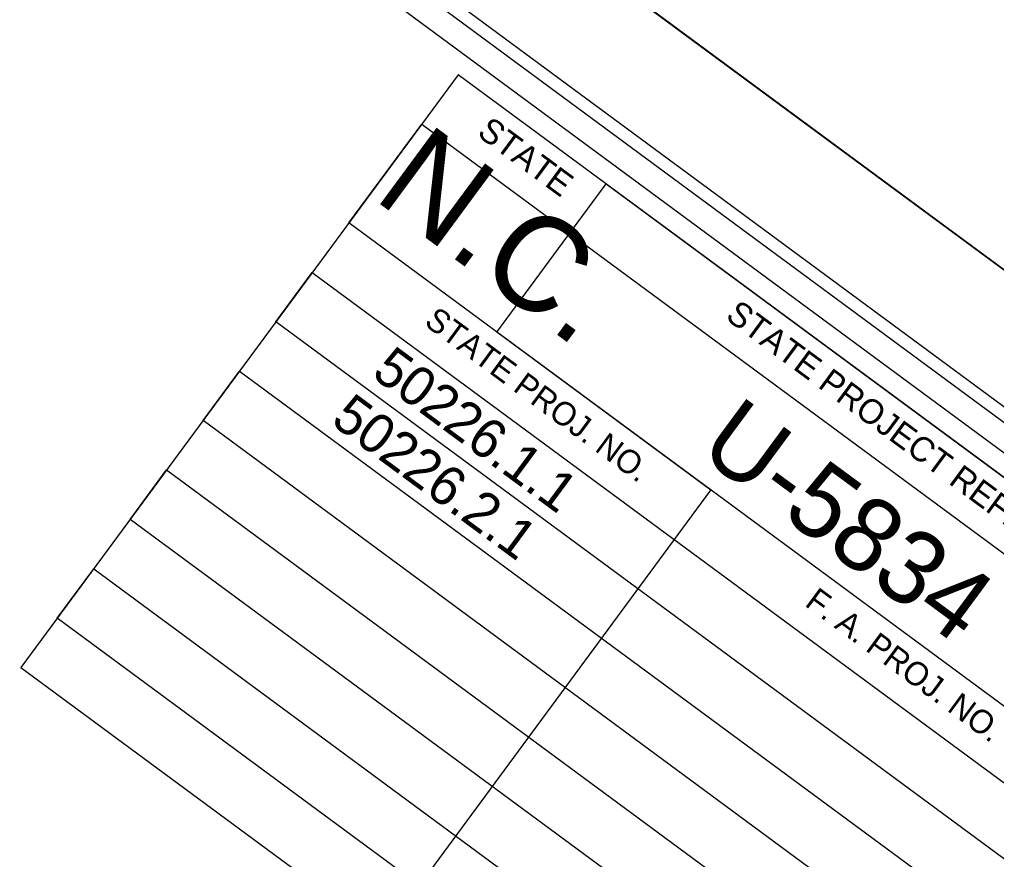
# Model space of a CAD drawing. Extents: x 945666 to 965748, y 644452 to 663300.
# Drawn here: x 962231 to 964220, y 653220 to 654930 of the extents above; entities that cross this region are included whole.
import ezdxf

# ---------------------------------------------------------------- set-up
doc = ezdxf.new("R2010")
doc.units = 0
for name, color, linetype in [('Sheet Cutting Line CELL', 7, 'Continuous'), ('Sheet Data Field CELL', 7, 'Continuous'), ('Sheet Plot Border Inside CELL', 7, 'Continuous'), ('Sheet Plot Border Outside CELL', 7, 'Continuous'), ('Sheet Title CELL', 7, 'Continuous')]:
    doc.layers.add(name, color=color, linetype=linetype)

msp = doc.modelspace()

# ---------------------------------------------------------------- linework, layer by layer
at = {"layer": 'Sheet Cutting Line CELL'}
msp.add_line((952195, 663300.2), (965747.9, 653304.9), dxfattribs=at)
at = {"layer": 'Sheet Plot Border Inside CELL'}
msp.add_lwpolyline([(945903.9, 654551), (959315.9, 644659.5), (965578.4, 653150.9), (952166.4, 663042.4)], close=True, dxfattribs=at)
at = {"layer": 'Sheet Plot Border Outside CELL'}
msp.add_lwpolyline([(965747.9, 653304.9), (952195, 663300.2), (945666.1, 654447.6), (959218.9, 644452.2)], close=True, dxfattribs=at)
at = {"layer": 'Sheet Title CELL'}
for points in [[(965382.3, 653263.9), (953471.1, 662048.6)], [(965312.3, 653253.4), (953884.2, 661681.7)], [(965336.9, 653185.7), (963123.6, 654817.8), (962233.4, 653610.8), (962970.9, 653066.7), (963638.6, 653972.1), (963202.8, 654293.5), (963425.5, 654595.4), (964733.3, 653630.7)], [(965114.3, 652883.9), (962901.1, 654516.2), (963049.5, 654717.3), (965262.7, 653085.1)], [(964965.8, 652682.6), (962752.6, 654314.8), (962826.8, 654415.4), (965040, 652783.2)], [(964817.5, 652481.5), (962604.3, 654113.8), (962678.4, 654214.2), (964891.7, 652582.1)], [(964669.1, 652280.2), (962456, 653912.4), (962530.1, 654013.2), (964743.3, 652380.9)], [(964520.7, 652079), (962307.5, 653711.4), (962381.7, 653811.9), (964594.9, 652179.6)], [(962233.4, 653610.8), (964446.5, 651978.5)]]:
    msp.add_lwpolyline(points, dxfattribs=at)

# ---------------------------------------------------------------- texts
at = {"layer": 'Sheet Data Field CELL'}
for s, height, p in [('50226.1.1', 80, (962944.8, 654204.8)), ('50226.2.1', 80, (962861.9, 654108.6)), ('U-5834', 150, (963609, 654046.1))]:
    msp.add_text(s, height=height, rotation=323.5908, dxfattribs=at).set_placement(p)
at = {"layer": 'Sheet Title CELL'}
for s, height, p in [('N.C.', 193.5, (962947.8, 654566.8)), ('STATE', 50, (963160.2, 654694.7)), ('STATE PROJECT REFERENCE NO.', 49.998, (963665.9, 654321.6)), ('STATE PROJ. NO.', 48, (963052.5, 654309.5)), ('F. A. PROJ. NO.', 48, (963827.5, 653737.9))]:
    msp.add_text(s, height=height, rotation=323.5908, dxfattribs=at).set_placement(p)

doc.saveas('drawing.dxf')
